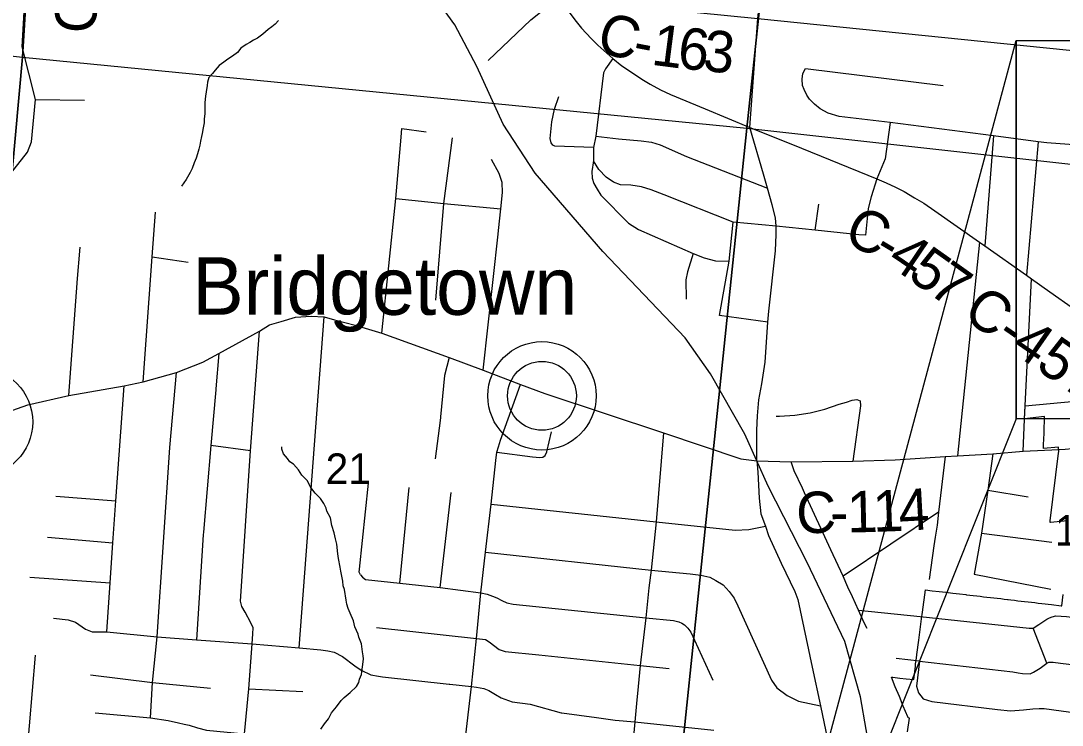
# Model space of a CAD drawing. Extents: x 0 to 34, y 0 to 22.
# Drawn here: x 6.05 to 7.479, y 19.576 to 20.543 of the extents above; entities that cross this region are included whole.
import ezdxf

# ---------------------------------------------------------------- set-up
doc = ezdxf.new("R2010")
doc.units = 0
for name, color, linetype in [('GM_X_City_Street', 7, 'Continuous'), ('GM_X_Corporation', 7, 'Continuous'), ('GM_X_County_Road', 7, 'Continuous'), ('GM_X_County_Road_Text', 7, 'Continuous'), ('GM_X_Minor_River', 7, 'Continuous'), ('GM_X_Rail_Line', 7, 'Continuous'), ('GM_X_Section_Text', 7, 'Continuous'), ('GM_X_State_Route', 7, 'Continuous'), ('GM_X_Township_Road', 7, 'Continuous'), ('GM_X_Unincorporated', 7, 'Continuous'), ('GM_X_Unincorporated_Location', 7, 'Continuous'), ('GM_X_Unincorporated_Text', 7, 'Continuous'), ('SH_Masking', 7, 'Continuous'), ('SH_Text', 7, 'Continuous')]:
    doc.layers.add(name, color=color, linetype=linetype)

msp = doc.modelspace()

# ---------------------------------------------------------------- linework, layer by layer
at = {"layer": 'GM_X_City_Street'}
msp.add_line((7.4584, 19.661), (7.4396, 19.7094), dxfattribs=at)
for points in [[(7.2842, 19.725), (7.4341, 19.7094), (7.4396, 19.7094), (7.4472, 19.7142), (7.4583, 19.7216), (7.462, 19.7234), (7.4657, 19.7249), (7.4706, 19.726), (7.485, 19.725), (7.5967, 19.7111)], [(7.2836, 19.6638), (7.2792, 19.6295), (7.2821, 19.6202), (7.2883, 19.612), (7.3005, 19.6086), (7.3904, 19.5974), (7.4084, 19.5959), (7.4261, 19.5973), (7.4388, 19.5986), (7.4478, 19.5989), (7.4545, 19.5991), (7.5244, 19.5891), (7.5808, 19.5831)], [(7.2836, 19.6638), (7.4114, 19.6493), (7.4186, 19.6481), (7.4249, 19.6469), (7.4352, 19.6467), (7.4397, 19.6488), (7.449, 19.6545), (7.4584, 19.661), (7.4611, 19.6623), (7.4667, 19.6626), (7.4768, 19.6613), (7.5892, 19.6479)]]:
    msp.add_lwpolyline(points, dxfattribs=at)
at = {"layer": 'GM_X_Corporation'}
for points in [[(6.077, 20.9), (5.0731, 20.9), (5.0456, 20.6041), (6.0521, 20.4929)], [(7.0997, 20.9), (6.077, 20.9), (6.0521, 20.4929), (7.0465, 20.3953)], [(8.1157, 20.9), (7.0997, 20.9), (7.0465, 20.3953), (8.0517, 20.2839)], [(6.0521, 20.4929), (5.9616, 19.4927), (4.9462, 19.5973), (5.0456, 20.6041)], [(7.0465, 20.3953), (6.9413, 19.3834), (5.9616, 19.4927), (6.0521, 20.4929)], [(7.0465, 20.3953), (8.0517, 20.2839), (7.955, 19.3167), (7.3077, 19.388), (7.3067, 19.3446), (6.9413, 19.3834)]]:
    msp.add_lwpolyline(points, close=True, dxfattribs=at)
for points in [[(7.4865, 19.8566), (7.463, 19.8544), (7.4627, 19.8544), (7.4627, 19.8545), (7.4628, 19.8565), (7.4744, 19.9492), (7.4747, 19.9518), (7.4744, 19.9578), (7.4536, 19.9557), (7.4538, 19.962), (7.454, 19.9675), (7.4543, 19.9776), (7.455, 19.9996), (7.4274, 19.9965), (7.4283, 20.0146), (7.497, 20.0208)], [(7.2671, 19.567), (7.2696, 19.5858), (7.2678, 19.586), (7.2673, 19.5873), (7.2611, 19.6022), (7.2557, 19.6153), (7.2501, 19.6288), (7.2448, 19.6419), (7.2468, 19.6417), (7.2562, 19.6407), (7.2653, 19.6396), (7.2757, 19.6385), (7.2777, 19.6564), (7.2778, 19.6575), (7.2781, 19.6602), (7.2787, 19.6649), (7.2797, 19.6726), (7.2798, 19.673), (7.2824, 19.6926), (7.2862, 19.7219), (7.2874, 19.7313), (7.2914, 19.7616), (7.3008, 19.7606), (7.3102, 19.7595), (7.3196, 19.7584), (7.329, 19.7573), (7.3384, 19.7562), (7.3471, 19.7552), (7.3478, 19.7551), (7.3572, 19.754), (7.3619, 19.7535), (7.3666, 19.7529), (7.3713, 19.7524), (7.376, 19.7519), (7.3807, 19.7513), (7.3854, 19.7508), (7.3901, 19.7502), (7.3948, 19.7497), (7.3995, 19.7491), (7.4043, 19.7486), (7.4052, 19.7485), (7.4089, 19.748), (7.4137, 19.7475), (7.4183, 19.7469), (7.4231, 19.7464), (7.4277, 19.7458), (7.4325, 19.7453), (7.4371, 19.7448), (7.4419, 19.7442), (7.4465, 19.7437), (7.4513, 19.7431), (7.4644, 19.7416), (7.4778, 19.74), (7.4786, 19.7399), (7.4806, 19.7553)]]:
    msp.add_lwpolyline(points, dxfattribs=at)
at = {"layer": 'GM_X_County_Road'}
for points in [[(6.0357, 20.3327), (6.0589, 20.3625), (6.0642, 20.3768), (6.0699, 20.4348), (6.0514, 20.507), (6.0739, 20.9)], [(6.5797, 20.9), (6.5922, 20.8807), (6.609, 20.8555), (6.6257, 20.828), (6.6385, 20.8086), (6.6511, 20.7887), (6.6599, 20.7739), (6.6778, 20.7443), (6.7353, 20.6548), (6.7877, 20.5749), (6.8101, 20.5442), (6.8193, 20.533), (6.8328, 20.5185), (6.8419, 20.5096), (6.8623, 20.4912), (6.8749, 20.4813), (6.8851, 20.4742), (6.902, 20.4629), (6.9135, 20.4559), (6.9278, 20.4482), (6.9415, 20.4415), (6.989, 20.4219), (7.0504, 20.3965)], [(6.7877, 20.5749), (6.803, 20.5835), (6.8139, 20.5861), (6.8329, 20.5848), (6.857, 20.5786), (6.8813, 20.5698), (6.9073, 20.564), (6.9367, 20.5585), (7.0614, 20.546), (7.5701, 20.4942), (7.7383, 20.4795), (7.8165, 20.4727), (7.8632, 20.4681), (7.8783, 20.4665)], [(7.0504, 20.3965), (7.0614, 20.546), (7.0645, 20.5751)], [(7.0602, 19.9389), (7.0602, 19.9628), (7.0602, 19.9809), (7.0609, 20.0006), (7.0628, 20.0228), (7.0668, 20.0446), (7.0713, 20.0741), (7.075, 20.129), (7.0767, 20.1441), (7.0855, 20.2273), (7.0867, 20.2494), (7.0864, 20.2609), (7.0855, 20.2724), (7.0811, 20.2905), (7.0747, 20.3133), (7.0694, 20.3325), (7.0504, 20.3965)], [(7.0504, 20.3965), (7.1089, 20.3731), (7.2246, 20.326), (7.2376, 20.3206), (7.2504, 20.3144), (7.2625, 20.3084), (7.2765, 20.3001), (7.2892, 20.2926), (7.3046, 20.2821), (7.3658, 20.239), (7.373, 20.2341), (7.4302, 20.1937), (7.4372, 20.1889), (7.4624, 20.1709), (7.5271, 20.1251)], [(7.0602, 19.9389), (7.1074, 19.9376), (7.1917, 19.9386), (7.2501, 19.9403), (7.3184, 19.945), (7.3355, 19.9457), (7.384, 19.9486), (7.4255, 19.9523), (7.4747, 19.9546)], [(7.4747, 19.9546), (7.4833, 19.955), (7.4929, 19.9557)]]:
    msp.add_lwpolyline(points, dxfattribs=at)
at = {"layer": 'GM_X_Minor_River'}
for points in [[(6.4033, 20.5433), (6.3989, 20.5381), (6.3943, 20.5345), (6.3892, 20.5308), (6.3818, 20.5246), (6.3747, 20.5192), (6.3689, 20.5163), (6.3639, 20.5131), (6.3589, 20.5102), (6.3519, 20.5051), (6.3471, 20.4996), (6.3401, 20.4945), (6.3339, 20.4902), (6.3284, 20.4862), (6.3222, 20.4815), (6.3163, 20.4752), (6.3127, 20.4704), (6.3076, 20.4649), (6.3062, 20.4585), (6.3057, 20.4539), (6.3042, 20.4456), (6.3033, 20.4396), (6.3022, 20.4308), (6.3024, 20.4244), (6.3021, 20.4157), (6.3014, 20.4077), (6.3012, 20.4028), (6.2999, 20.396), (6.2985, 20.3884), (6.2976, 20.3839), (6.2962, 20.3778), (6.2953, 20.3722), (6.2939, 20.3665), (6.2922, 20.3601), (6.2905, 20.3545), (6.2876, 20.3477), (6.285, 20.3402), (6.2822, 20.3346), (6.2769, 20.3249), (6.2737, 20.3205), (6.2701, 20.3157)], [(6.4917, 19.7736), (6.4892, 19.7874), (6.4879, 19.7927), (6.486, 19.8046), (6.4851, 19.8114), (6.4833, 19.8244), (6.4816, 19.8317), (6.48, 19.8401), (6.4765, 19.8501), (6.4746, 19.8605), (6.4696, 19.8698), (6.469, 19.874), (6.4655, 19.8805), (6.4611, 19.8872), (6.4538, 19.8946), (6.448, 19.9024), (6.443, 19.9121), (6.4357, 19.9192), (6.431, 19.9266), (6.424, 19.9341), (6.4188, 19.9373), (6.4156, 19.9423), (6.4101, 19.9486), (6.408, 19.9548), (6.4078, 19.9583)], [(6.4616, 19.5705), (6.4664, 19.578), (6.4723, 19.5846), (6.476, 19.5928), (6.4831, 19.6013), (6.4895, 19.6098), (6.4938, 19.6139), (6.5017, 19.6208), (6.5103, 19.6293), (6.5135, 19.6345), (6.5148, 19.639), (6.5173, 19.6458), (6.5183, 19.6529), (6.5193, 19.6594), (6.52, 19.6669), (6.5197, 19.6711), (6.5188, 19.6769), (6.5173, 19.6879), (6.5138, 19.6968), (6.5128, 19.701), (6.5082, 19.7111), (6.5062, 19.7191), (6.5016, 19.7299), (6.4992, 19.7361), (6.4971, 19.7422), (6.4962, 19.7476), (6.494, 19.7621), (6.4923, 19.7675), (6.4917, 19.7736)]]:
    msp.add_lwpolyline(points, dxfattribs=at)
at = {"layer": 'GM_X_Rail_Line'}
msp.add_lwpolyline([(7.2074, 18.8505), (7.1644, 18.9863), (7.1583, 19.0746), (7.1652, 19.1716), (7.1865, 19.2574), (7.219, 19.4134), (7.2179, 19.5252), (7.2022, 19.6149), (7.1807, 19.691), (7.1291, 19.7994), (7.0756, 19.9039), (7.0435, 19.9756), (6.9966, 20.0583), (6.9615, 20.1077), (6.8485, 20.226), (6.7559, 20.3339), (6.7119, 20.4011), (6.6759, 20.48), (6.6457, 20.5375), (6.5931, 20.6104)], dxfattribs=at)
at = {"layer": 'GM_X_State_Route'}
for points in [[(6.0309, 20.0057), (6.0594, 20.0158), (6.1157, 20.0286), (6.1915, 20.0418), (6.2178, 20.0473), (6.2635, 20.0599), (6.2994, 20.0745), (6.3215, 20.0864), (6.3775, 20.117), (6.3909, 20.1256), (6.4069, 20.1302), (6.4268, 20.1359), (6.4482, 20.1374), (6.4662, 20.1364), (6.4805, 20.1326), (6.5086, 20.125), (6.5455, 20.1142), (6.6379, 20.0807), (6.6843, 20.0632), (6.7356, 20.0437), (6.7689, 20.0311), (6.932, 19.9774), (7.0383, 19.9417), (7.0602, 19.9389)], [(7.0602, 19.9389), (7.0616, 19.9231), (7.0631, 19.8876), (7.0657, 19.8662), (7.0718, 19.8491), (7.0763, 19.8364), (7.0936, 19.7984), (7.1124, 19.7596), (7.1163, 19.7485), (7.1361, 19.6557), (7.1474, 19.6024), (7.1549, 19.5672), (7.1606, 19.5375), (7.1591, 19.4991), (7.1588, 19.4912), (7.158, 19.4508)]]:
    msp.add_lwpolyline(points, dxfattribs=at)
at = {"layer": 'GM_X_Township_Road'}
for p, q in [((7.127, 20.4775), (7.3158, 20.454)), ((6.0699, 20.4348), (6.137, 20.4338)), ((7.385, 20.3852), (7.373, 20.2341)), ((7.4464, 20.3769), (7.4302, 20.1937)), ((7.1403, 20.2557), (7.1451, 20.2912)), ((6.1272, 20.1837), (6.1314, 20.2323)), ((7.3658, 20.239), (7.3355, 19.9457)), ((6.2302, 20.2188), (6.2793, 20.2116)), ((7.4285, 20.0144), (7.4372, 20.1889)), ((6.4319, 19.6821), (6.4662, 20.1364)), ((7.075, 20.129), (7.0087, 20.1384)), ((6.3215, 20.0864), (6.3173, 20.0375)), ((7.4276, 19.9957), (7.4285, 20.0144)), ((7.4255, 19.9523), (7.4276, 19.9957)), ((6.3648, 19.9528), (6.3106, 19.9597)), ((7.3184, 19.945), (7.3093, 19.8684)), ((6.5699, 19.771), (6.5827, 19.9023)), ((6.0977, 19.8904), (6.1803, 19.8841)), ((6.6253, 19.7652), (6.6405, 19.8955)), ((7.3771, 19.8986), (7.4325, 19.8896)), ((7.3093, 19.8684), (7.1786, 19.7804)), ((6.0864, 19.8343), (6.1762, 19.8263)), ((7.3685, 19.8394), (7.4651, 19.8273)), ((6.0621, 19.7793), (6.1723, 19.7713)), ((7.3586, 19.7835), (7.4638, 19.7627)), ((7.1995, 19.734), (7.2842, 19.725)), ((7.2114, 19.7086), (7.2085, 19.7146)), ((7.2836, 19.6638), (7.2512, 19.6676)), ((6.3625, 19.6258), (6.437, 19.6222))]:
    msp.add_line(p, q, dxfattribs=at)
for points in [[(6.6912, 20.4885), (6.7499, 20.5442), (6.7877, 20.5749)], [(6.8623, 20.4912), (6.8522, 20.477), (6.8497, 20.4715), (6.8392, 20.3845), (6.8358, 20.369), (6.8358, 20.3508), (6.8336, 20.3362), (6.8341, 20.327), (6.8363, 20.3196), (6.8408, 20.3117), (6.8461, 20.3034), (6.8839, 20.265), (6.8978, 20.2564), (6.9728, 20.2237), (6.9879, 20.2177), (7.0033, 20.2136), (7.022, 20.2131)], [(7.1249, 20.4484), (7.1227, 20.4542), (7.1225, 20.4628), (7.1232, 20.4707), (7.127, 20.4775)], [(7.5565, 20.3681), (7.4581, 20.3753), (7.4464, 20.3769), (7.385, 20.3852), (7.2433, 20.4035), (7.1732, 20.4114), (7.1581, 20.4162), (7.1468, 20.4219), (7.1393, 20.4284), (7.1324, 20.4352), (7.1288, 20.4407), (7.1249, 20.4484)], [(6.8358, 20.369), (6.7827, 20.3709), (6.7801, 20.3721), (6.7779, 20.3756), (6.7762, 20.3813), (6.7785, 20.4044), (6.7825, 20.4214), (6.7884, 20.4391)], [(7.2433, 20.4035), (7.2362, 20.3532), (7.2246, 20.326), (7.217, 20.3014), (7.213, 20.2854), (7.2091, 20.2486), (7.1999, 20.2493), (7.1871, 20.2504), (7.1403, 20.2557), (7.0864, 20.2609), (7.0275, 20.2667), (6.9327, 20.3042), (6.9148, 20.3109), (6.9017, 20.315), (6.8873, 20.3172), (6.873, 20.3177), (6.8635, 20.3212), (6.8533, 20.3284), (6.8433, 20.3386), (6.8358, 20.3508)], [(6.5719, 20.383), (6.5727, 20.3949), (6.6061, 20.3907)], [(6.5455, 20.1142), (6.5647, 20.2991), (6.5719, 20.383)], [(6.6196, 20.1592), (6.6304, 20.2923), (6.6421, 20.3822)], [(6.8392, 20.3845), (6.8704, 20.3809), (6.9011, 20.3782), (6.9154, 20.3761), (6.9274, 20.3727), (6.9637, 20.3564), (7.0747, 20.3133)], [(6.7056, 20.2549), (6.7087, 20.2849), (6.7108, 20.3074), (6.7103, 20.3208), (6.7063, 20.3333), (6.6959, 20.3527)], [(6.5647, 20.2991), (6.6304, 20.2923), (6.7087, 20.2849)], [(6.2178, 20.0473), (6.2302, 20.2188), (6.2346, 20.2802)], [(7.0087, 20.1384), (7.022, 20.2131), (7.0275, 20.2667)], [(6.6843, 20.0632), (6.705, 20.2499), (6.7056, 20.2549)], [(6.9728, 20.2237), (6.9648, 20.1984), (6.9627, 20.1874), (6.9631, 20.161)], [(6.1157, 20.0286), (6.1272, 20.1827), (6.1272, 20.1837)], [(6.3486, 19.4465), (6.3519, 19.5047), (6.3566, 19.564), (6.3625, 19.6258), (6.3673, 19.6875), (6.3684, 19.7015), (6.3686, 19.7095), (6.3654, 19.7164), (6.3579, 19.731), (6.3531, 19.739), (6.3512, 19.7463), (6.3648, 19.9528), (6.3775, 20.117)], [(6.6379, 20.0807), (6.6315, 20.056), (6.626, 19.9995), (6.6258, 19.998)], [(6.2368, 19.6973), (6.2543, 19.957), (6.2635, 20.0599)], [(6.1677, 19.704), (6.1723, 19.7713), (6.1762, 19.8263), (6.1803, 19.8841), (6.1915, 20.0418)], [(6.6587, 19.5474), (6.6682, 19.629), (6.6754, 19.6951), (6.6814, 19.7575), (6.6878, 19.8136), (6.6956, 19.8796), (6.7019, 19.9395), (6.7031, 19.9506), (6.7056, 19.958), (6.7081, 19.9674), (6.7356, 20.0437)], [(6.3173, 20.0375), (6.3172, 20.0365), (6.3106, 19.9597), (6.3004, 19.841)], [(7.0866, 20.0002), (7.0911, 20.0002), (7.1122, 20.0016), (7.1332, 20.0049), (7.1534, 20.0099), (7.1731, 20.0168), (7.1833, 20.0194), (7.1909, 20.0223), (7.1974, 20.023), (7.2021, 20.0211), (7.2024, 20.0144), (7.1917, 19.9386)], [(6.6258, 19.998), (6.6239, 19.9836), (6.6184, 19.9417)], [(6.7031, 19.9506), (6.752, 19.9444), (6.7622, 19.9433), (6.7664, 19.9438), (6.7695, 19.9463), (6.7719, 19.9513), (6.7782, 19.9787)], [(6.932, 19.9774), (6.9217, 19.8553), (6.9148, 19.7889)], [(7.384, 19.9486), (7.3771, 19.8986), (7.3685, 19.8394), (7.3586, 19.7835)], [(7.1256, 19.895), (7.1227, 19.9012), (7.1114, 19.9252), (7.1074, 19.9376)], [(6.5159, 19.7823), (6.5142, 19.7861), (6.5145, 19.7903), (6.5269, 19.9082)], [(7.1912, 19.752), (7.1848, 19.7656), (7.1786, 19.7804), (7.1618, 19.8169), (7.1256, 19.895)], [(6.6956, 19.8796), (6.9217, 19.8553), (7.0303, 19.8439), (7.0492, 19.8448), (7.0718, 19.8491)], [(7.3093, 19.8684), (7.3077, 19.8504), (7.305, 19.834)], [(6.3004, 19.841), (6.3001, 19.8371), (6.291, 19.6931)], [(7.305, 19.834), (7.3032, 19.8223), (7.2967, 19.7762)], [(6.6878, 19.8136), (6.9148, 19.7889), (6.9687, 19.7836), (6.9833, 19.7821), (6.9954, 19.7791), (7.004, 19.7747), (7.0139, 19.7686), (7.0223, 19.7595), (7.0291, 19.7502), (7.0338, 19.7398), (7.0802, 19.6377), (7.0877, 19.6273), (7.1017, 19.6166), (7.1174, 19.6088), (7.1474, 19.6024)], [(6.9148, 19.7889), (6.9117, 19.7645), (6.9075, 19.7233), (6.8999, 19.6579), (6.897, 19.6289)], [(6.5159, 19.7823), (6.5186, 19.779), (6.523, 19.776), (6.5699, 19.771), (6.6253, 19.7652), (6.6814, 19.7575), (6.6897, 19.7557), (6.6972, 19.7533), (6.7031, 19.7509), (6.71, 19.7471), (6.717, 19.744), (6.7258, 19.7422), (6.9075, 19.7233), (6.9456, 19.7196), (6.9529, 19.7179), (6.9573, 19.7161), (6.9609, 19.7136), (6.9654, 19.7093), (6.9697, 19.7039), (6.9998, 19.6379)], [(7.2085, 19.7146), (7.2057, 19.7206), (7.1995, 19.734), (7.1912, 19.752)], [(6.0946, 19.7228), (6.1146, 19.7205), (6.1249, 19.7172), (6.1387, 19.7078), (6.1477, 19.7042), (6.1677, 19.704), (6.2368, 19.6973), (6.291, 19.6931), (6.3673, 19.6875), (6.4319, 19.6821), (6.4614, 19.6796), (6.4713, 19.6781), (6.48, 19.6762), (6.4913, 19.6703), (6.5081, 19.6574), (6.5169, 19.6515), (6.5302, 19.645), (6.5405, 19.6433)], [(6.5379, 19.7103), (6.6754, 19.6951), (6.6874, 19.6938), (6.6928, 19.6902), (6.7064, 19.68), (6.7145, 19.6772), (6.7608, 19.6724)], [(6.2277, 19.5861), (6.2305, 19.6346), (6.2368, 19.6973)], [(6.1638, 19.3976), (6.0692, 19.407), (6.064, 19.4098), (6.0591, 19.4134), (6.0548, 19.4192), (6.0513, 19.4281), (6.0501, 19.4399), (6.0534, 19.4781), (6.0699, 19.6721)], [(6.7608, 19.6724), (6.8999, 19.6579), (6.9398, 19.6539)], [(6.1454, 19.6453), (6.2305, 19.6346), (6.3101, 19.6267)], [(6.5405, 19.6433), (6.5461, 19.6423), (6.6376, 19.6324), (6.6386, 19.6323)], [(6.6386, 19.6323), (6.6682, 19.629), (6.6753, 19.6284), (6.6852, 19.6262), (6.6923, 19.6236), (6.7011, 19.6183), (6.7089, 19.6134), (6.7241, 19.6082), (6.7491, 19.605), (6.7915, 19.5931), (6.7925, 19.593)], [(6.897, 19.6289), (6.8948, 19.6057), (6.8924, 19.5805), (6.887, 19.5195), (6.8793, 19.4597), (6.8713, 19.3848)], [(6.1518, 19.5931), (6.2277, 19.5861), (6.2521, 19.5826), (6.266, 19.5791), (6.2738, 19.5774), (6.2807, 19.5759), (6.2922, 19.5724), (6.3048, 19.569), (6.3566, 19.564), (6.4327, 19.5567), (6.4529, 19.5556), (6.4683, 19.5545), (6.489, 19.5584), (6.5062, 19.5612), (6.5176, 19.5618), (6.5426, 19.561), (6.6587, 19.5474), (6.7664, 19.5358), (6.7843, 19.5328), (6.8271, 19.5258), (6.887, 19.5195), (6.8989, 19.5182), (7.1591, 19.4991)], [(6.7925, 19.593), (6.8398, 19.5864), (6.8625, 19.5834)], [(6.8625, 19.5834), (6.8655, 19.583), (6.8924, 19.5805), (7.0011, 19.569)]]:
    msp.add_lwpolyline(points, dxfattribs=at)
at = {"layer": 'GM_X_Unincorporated'}
for centre, radius in [((6.7651, 20.0281), 0.0744), ((6.7651, 20.0281), 0.0472), ((5.9917, 19.9923), 0.0744)]:
    msp.add_circle(centre, radius, dxfattribs=at)
at = {"layer": 'GM_X_Unincorporated_Location'}
msp.add_line((6.7651, 20.0281), (6.7651, 20.0281), dxfattribs=at)
at = {"layer": 'SH_Masking'}
msp.add_lwpolyline([(7.4161, 20.5159), (9.1735, 20.5159), (9.1735, 19.9965), (7.4161, 19.9965)], close=True, dxfattribs=at)
at = {"layer": 'SH_Text'}
for points in [[(7.4161, 19.9965), (6.9921, 18.934), (7.4161, 20.5159)], [(7.4161, 20.5159), (9.1735, 20.5159), (9.1735, 19.9965), (7.4161, 19.9965)]]:
    msp.add_lwpolyline(points, close=True, dxfattribs=at)

# ---------------------------------------------------------------- texts
at = {"layer": 'GM_X_County_Road_Text'}
for s, height, rotation, p in [('C-161', 0.05682, 86.6984, (6.1521, 20.5245)), ('C', 0.0568, 343.9721, (6.8375, 20.5019)), ('1', 0.0568, 352.608, (6.9139, 20.4828)), ('6', 0.0568, 353.9378, (6.9498, 20.4782)), ('3', 0.0568, 354.1548, (6.9846, 20.4745)), ('-', 0.0568, 349.1438, (6.8875, 20.4878)), ('C', 0.0568, 334.8407, (7.1768, 20.2399)), ('4', 0.0568, 325.9216, (7.2366, 20.2096)), ('-', 0.0568, 329.2287, (7.2174, 20.2209)), ('5', 0.0568, 324.7539, (7.2651, 20.1903)), ('7', 0.0568, 324.5553, (7.2934, 20.1703)), ('C-457', 0.05682, 325.1651, (7.3404, 20.1364)), ('1', 0.0568, 2.1479, (7.2201, 19.8412)), ('4', 0.0568, 3.2223, (7.256, 19.8425)), ('C', 0.0568, 0.6766, (7.1144, 19.8395)), ('1', 0.0568, 1.2816, (7.1845, 19.8404)), ('-', 0.0568, 0.8269, (7.1609, 19.84))]:
    msp.add_text(s, height=height, rotation=rotation, dxfattribs=at).set_placement(p)
at = {"layer": 'GM_X_Section_Text'}
for s, p in [('21', (6.4681, 19.9072)), ('15', (7.4693, 19.8225))]:
    msp.add_text(s, height=0.04186, rotation=0, dxfattribs=at).set_placement(p)
at = {"layer": 'GM_X_Unincorporated_Text'}
msp.add_text('Bridgetown', height=0.07898, rotation=0, dxfattribs=at).set_placement((6.2852, 20.1393))

doc.saveas('drawing.dxf')
